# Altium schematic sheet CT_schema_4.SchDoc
size 301 x 258 mm
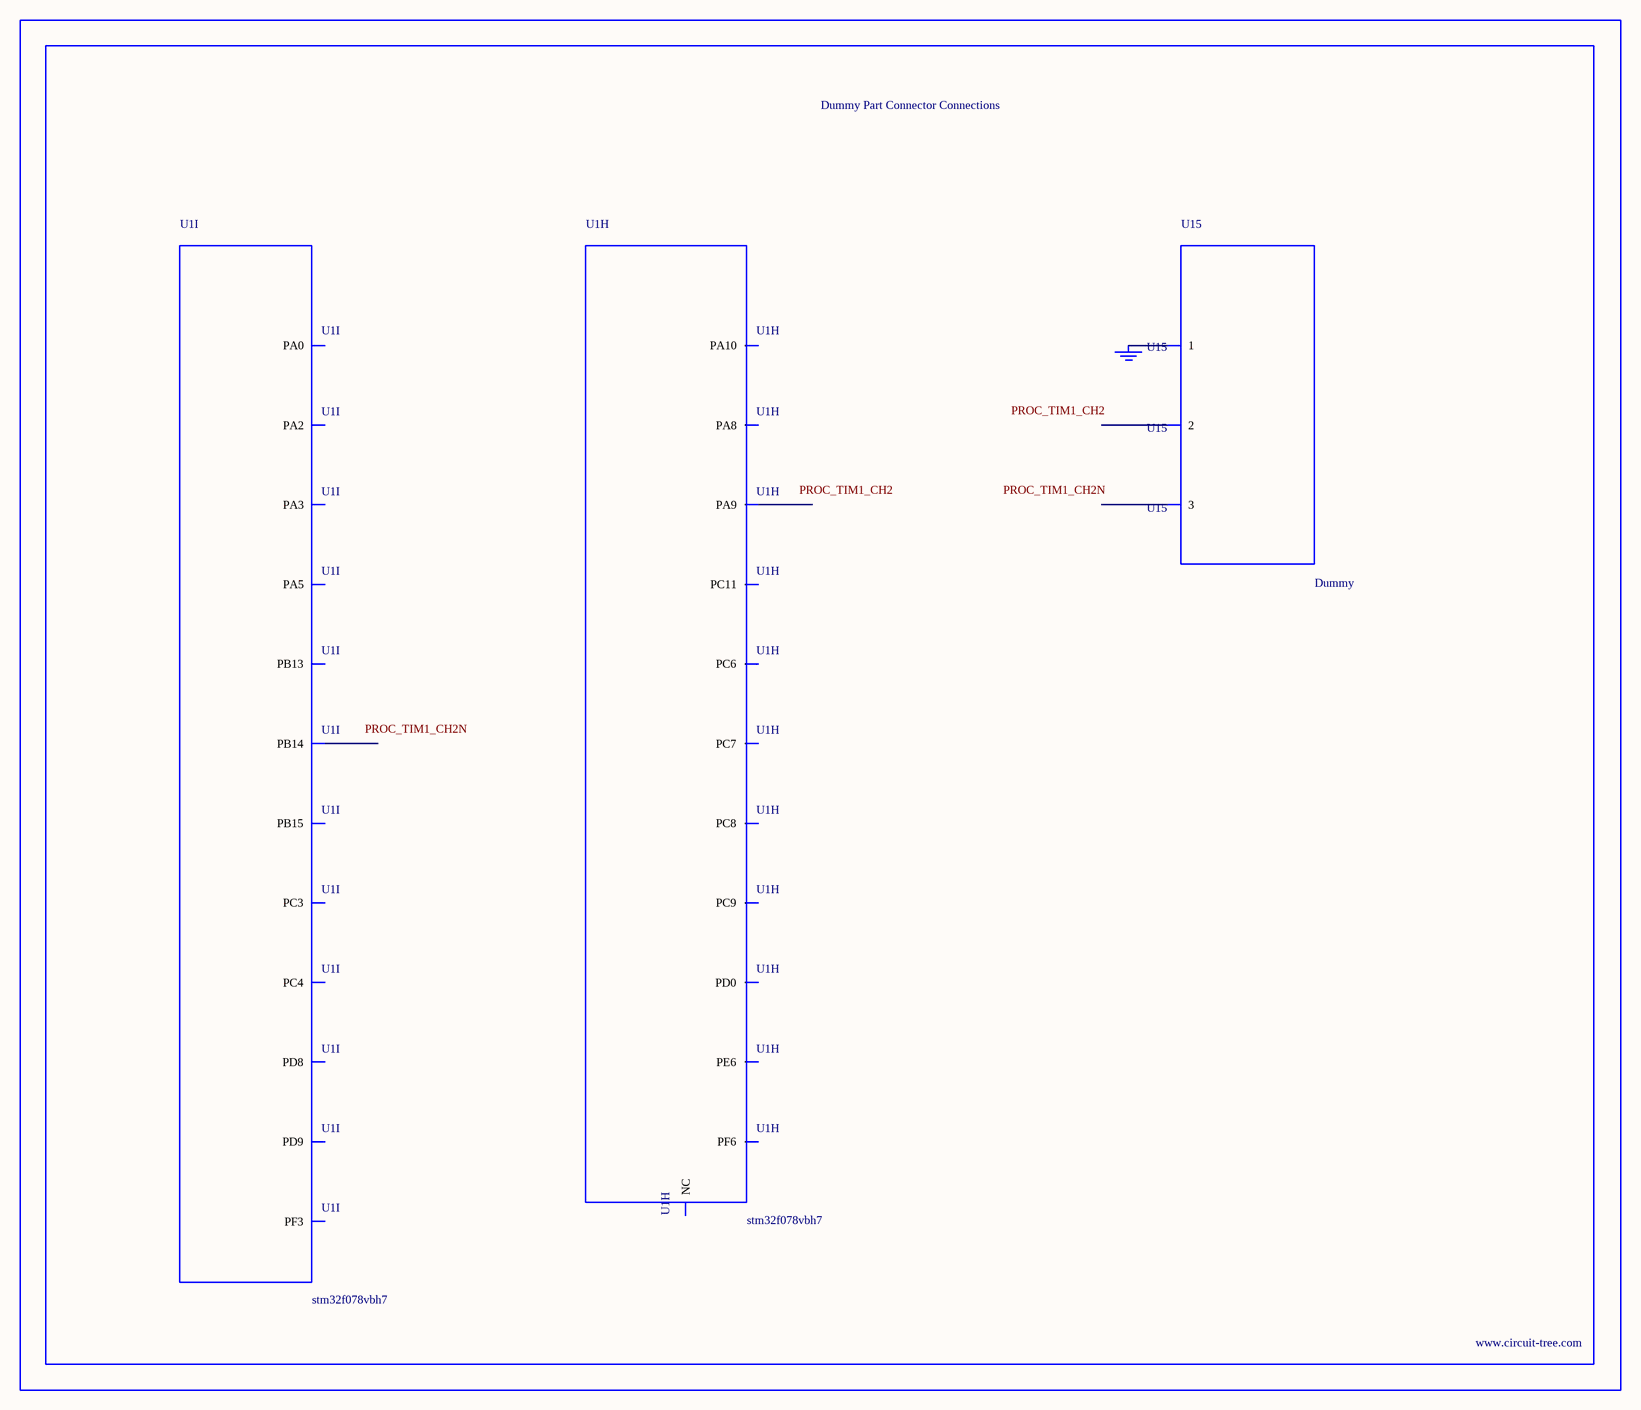
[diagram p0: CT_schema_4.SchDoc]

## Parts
BORDER3  (no value)
GND_INSTANCE_3_0  (no value)
U1  stm32f078vbh7  [UFBGA100]  (parts H,I of 9)
U15  Dummy  [DUMMY_PACKAGE_116]

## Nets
NetGND_INSTANCE_3_0_0: GND_INSTANCE_3_0.0(GND) U15.1

Not connected (* = marked no-connect by the designer): U1 C9(PD0) C10(PC11) C11(PF6) C12(PA10) D2(PE6) D10(PA9) D11(PA8) D12(PC9) E3(NC) E10(PC8) E11(PC7) E12(PC6) K2(PC3) K3(PA2) K4(PA5) K5(PC4) K8(PD9) K9(PD8) K10(PB15) K11(PB14) K12(PB13) L1(PF3) L2(PA0) L3(PA3); U15 2 3

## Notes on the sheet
- Labels drawn without touching a wire or pin: PROC_TIM1_CH2, PROC_TIM1_CH2N

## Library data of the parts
BORDER3 = BORDER_PAGE3
GND_INSTANCE_3_0 = GND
